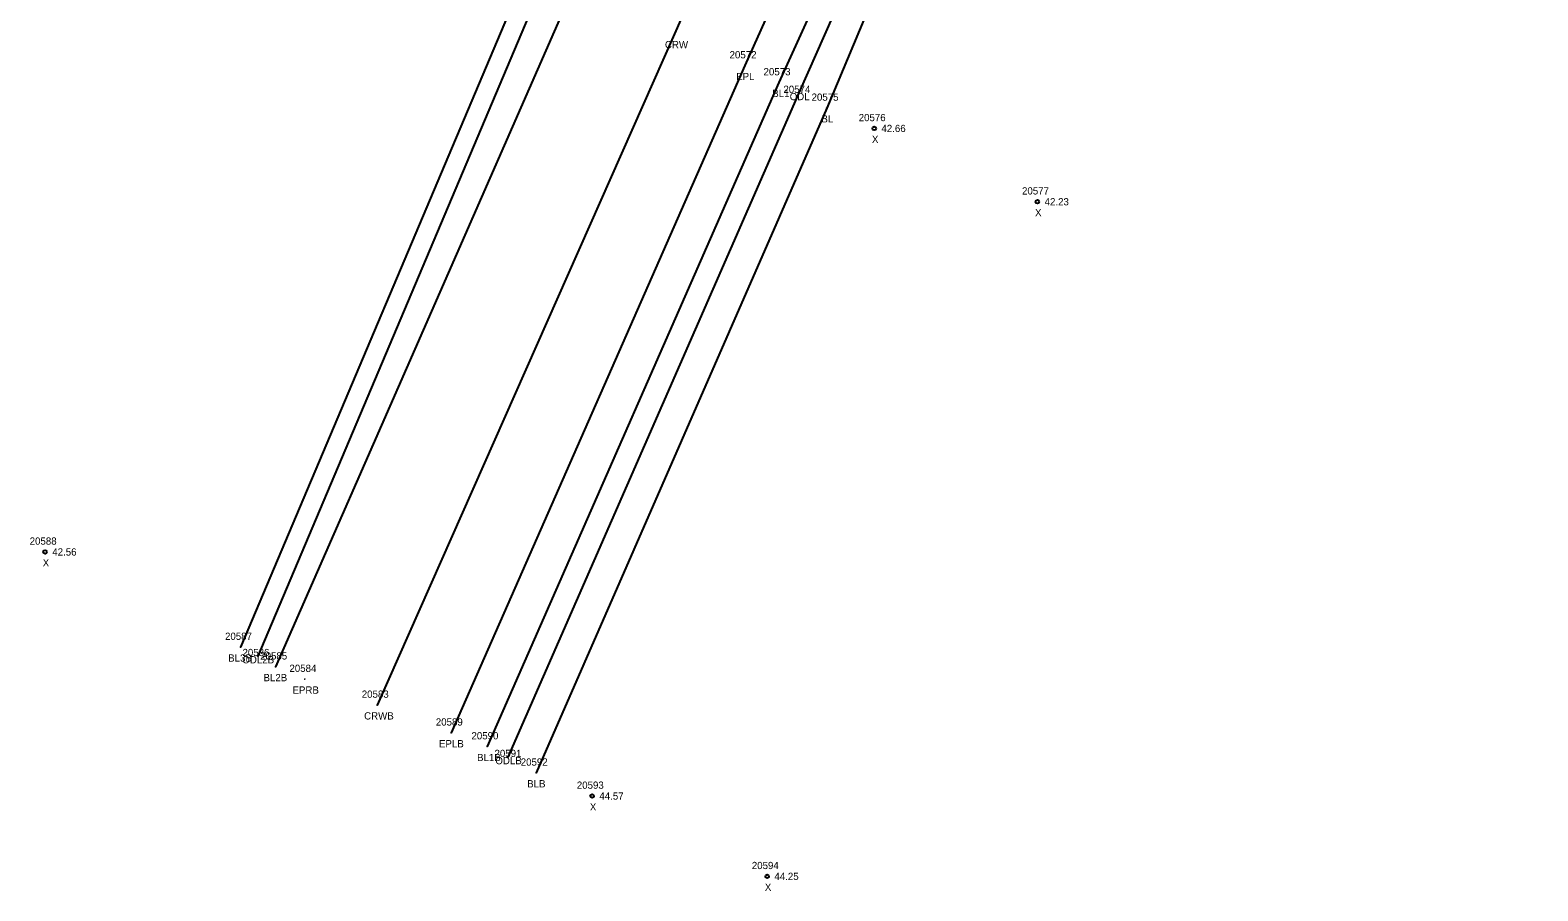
# Model space of a CAD drawing. Extents: x 2432729 to 2433340, y 684958 to 688103.
# Drawn here: x 2432729.2 to 2432937.3, y 684957.8 to 685076.6 of the extents above; entities that cross this region are included whole.
import ezdxf

# ---------------------------------------------------------------- set-up
doc = ezdxf.new("R2010")
doc.units = 0
for name, color, linetype in [('RD_DTM_BkLn1', 7, 'Continuous'), ('RD_EX_H2O', 7, 'Continuous'), ('RD_EX_H2O_txCode', 7, 'Continuous'), ('RD_EX_Road', 7, 'Continuous'), ('RD_EX_Road_txCode', 7, 'Continuous'), ('RD_Sketch8', 7, 'Continuous'), ('RD_SMD_Locator', 7, 'Continuous'), ('RD_SMD_Misc', 7, 'Continuous')]:
    doc.layers.add(name, color=color, linetype=linetype)

msp = doc.modelspace()

# ---------------------------------------------------------------- linework, layer by layer
at = {"layer": 'RD_DTM_BkLn1'}
for points in [[(2433067.41, 685690.62), (2433052.49, 685638.4), (2433035.04, 685585.7), (2433018.41, 685541.16), (2432999.85, 685493.3), (2432978.77, 685442.62), (2432938.71, 685349.86), (2432898.27, 685257.39), (2432861.69, 685174.74), (2432859.51, 685169.85), (2432818.13, 685076.09), (2432777.09, 684983.43)], [(2432851.47, 685194.17), (2432846.48, 685195.94), (2432797.77, 685084.86), (2432758.22, 684991.42)], [(2432851.47, 685194.17), (2432803.82, 685081.7), (2432763.08, 684988.71)], [(2432882.72, 685169.92), (2432878.77, 685171.1), (2432832.54, 685069.35), (2432792.27, 684977.69)], [(2432882.72, 685169.92), (2432839.17, 685065.84), (2432799.03, 684974.06)]]:
    msp.add_lwpolyline(points, dxfattribs=at)
at = {"layer": 'RD_EX_H2O'}
for points in [[(2432848.72, 685193.33), (2432799.98, 685083.21), (2432760.65, 684990.18)], [(2432879.4, 685167.7), (2432835.28, 685067.92), (2432795.13, 684976.25)]]:
    msp.add_lwpolyline(points, dxfattribs=at)
at = {"layer": 'RD_EX_Road'}
msp.add_lwpolyline([(2433077.66, 685687.92), (2433062.23, 685635.7), (2433044.84, 685582.68), (2433028.22, 685537.07), (2433009.68, 685489.83), (2432988.53, 685438.27), (2432948.62, 685345.62), (2432907.86, 685252.74), (2432887.37, 685205.96), (2432872.08, 685170.45), (2432827.85, 685071.69), (2432787.31, 684979.59)], dxfattribs=at)
at = {"layer": 'RD_SMD_Locator'}
for centre, radius in [((2432818.13, 685076.09), 0.001), ((2432827.85, 685071.69), 0.001), ((2432832.54, 685069.35), 0.001), ((2432835.28, 685067.92), 0.001), ((2432839.17, 685065.84), 0.001), ((2432845.69, 685063.02), 0.25), ((2432868.21, 685052.9), 0.25), ((2432731.26, 685004.56), 0.25), ((2432758.22, 684991.42), 0.001), ((2432760.65, 684990.18), 0.001), ((2432763.08, 684988.71), 0.001), ((2432767.11, 684987), 0.001), ((2432777.09, 684983.43), 0.001), ((2432787.31, 684979.59), 0.001), ((2432792.27, 684977.69), 0.001), ((2432795.13, 684976.25), 0.001), ((2432799.03, 684974.06), 0.001), ((2432806.76, 684970.87), 0.25), ((2432830.92, 684959.78), 0.25)]:
    msp.add_circle(centre, radius, dxfattribs=at)

# ---------------------------------------------------------------- texts
at = {"layer": 'RD_EX_H2O_txCode'}
for s, p in [('20574', (2432833.16, 685067.92)), ('ODL', (2432834.03, 685066.92)), ('20586', (2432758.51, 684990.18)), ('ODL2B', (2432758.49, 684989.18)), ('20591', (2432793.29, 684976.25)), ('ODLB', (2432793.41, 684975.25))]:
    msp.add_text(s, height=1, dxfattribs=at).set_placement(p)
at = {"layer": 'RD_EX_Road_txCode'}
for s, p in [('20572', (2432825.73, 685072.69)), ('EPL', (2432826.64, 685069.69)), ('20584', (2432764.99, 684988)), ('EPRB', (2432765.41, 684985)), ('20589', (2432785.19, 684980.59)), ('EPLB', (2432785.63, 684977.59))]:
    msp.add_text(s, height=1, dxfattribs=at).set_placement(p)
at = {"layer": 'RD_Sketch8'}
for s, p in [('20576', (2432843.55, 685064.02)), ('X', (2432845.38, 685061.02)), ('42.66', (2432846.69, 685062.52)), ('20577', (2432866.09, 685053.9)), ('42.23', (2432869.21, 685052.4)), ('X', (2432867.89, 685050.9)), ('20588', (2432729.14, 685005.56)), ('X', (2432730.94, 685002.56)), ('42.56', (2432732.26, 685004.06)), ('20593', (2432804.65, 684971.87)), ('44.57', (2432807.76, 684970.37)), ('X', (2432806.45, 684968.87)), ('20594', (2432828.8, 684960.78)), ('44.25', (2432831.92, 684959.28)), ('X', (2432830.6, 684957.78))]:
    msp.add_text(s, height=1, dxfattribs=at).set_placement(p)
at = {"layer": 'RD_SMD_Misc'}
for s, p in [('CRW', (2432816.81, 685074.09)), ('20573', (2432830.42, 685070.35)), ('BL1', (2432831.62, 685067.35)), ('20575', (2432837.05, 685066.84)), ('BL', (2432838.41, 685063.84)), ('20587', (2432756.1, 684992.42)), ('BL3B', (2432756.54, 684989.42)), ('20585', (2432760.96, 684989.71)), ('BL2B', (2432761.41, 684986.71)), ('20583', (2432774.97, 684984.43)), ('CRWB', (2432775.3, 684981.43)), ('20590', (2432790.11, 684978.69)), ('BL1B', (2432790.88, 684975.69)), ('20592', (2432796.91, 684975.06)), ('BLB', (2432797.8, 684972.06))]:
    msp.add_text(s, height=1, dxfattribs=at).set_placement(p)

doc.saveas('drawing.dxf')
